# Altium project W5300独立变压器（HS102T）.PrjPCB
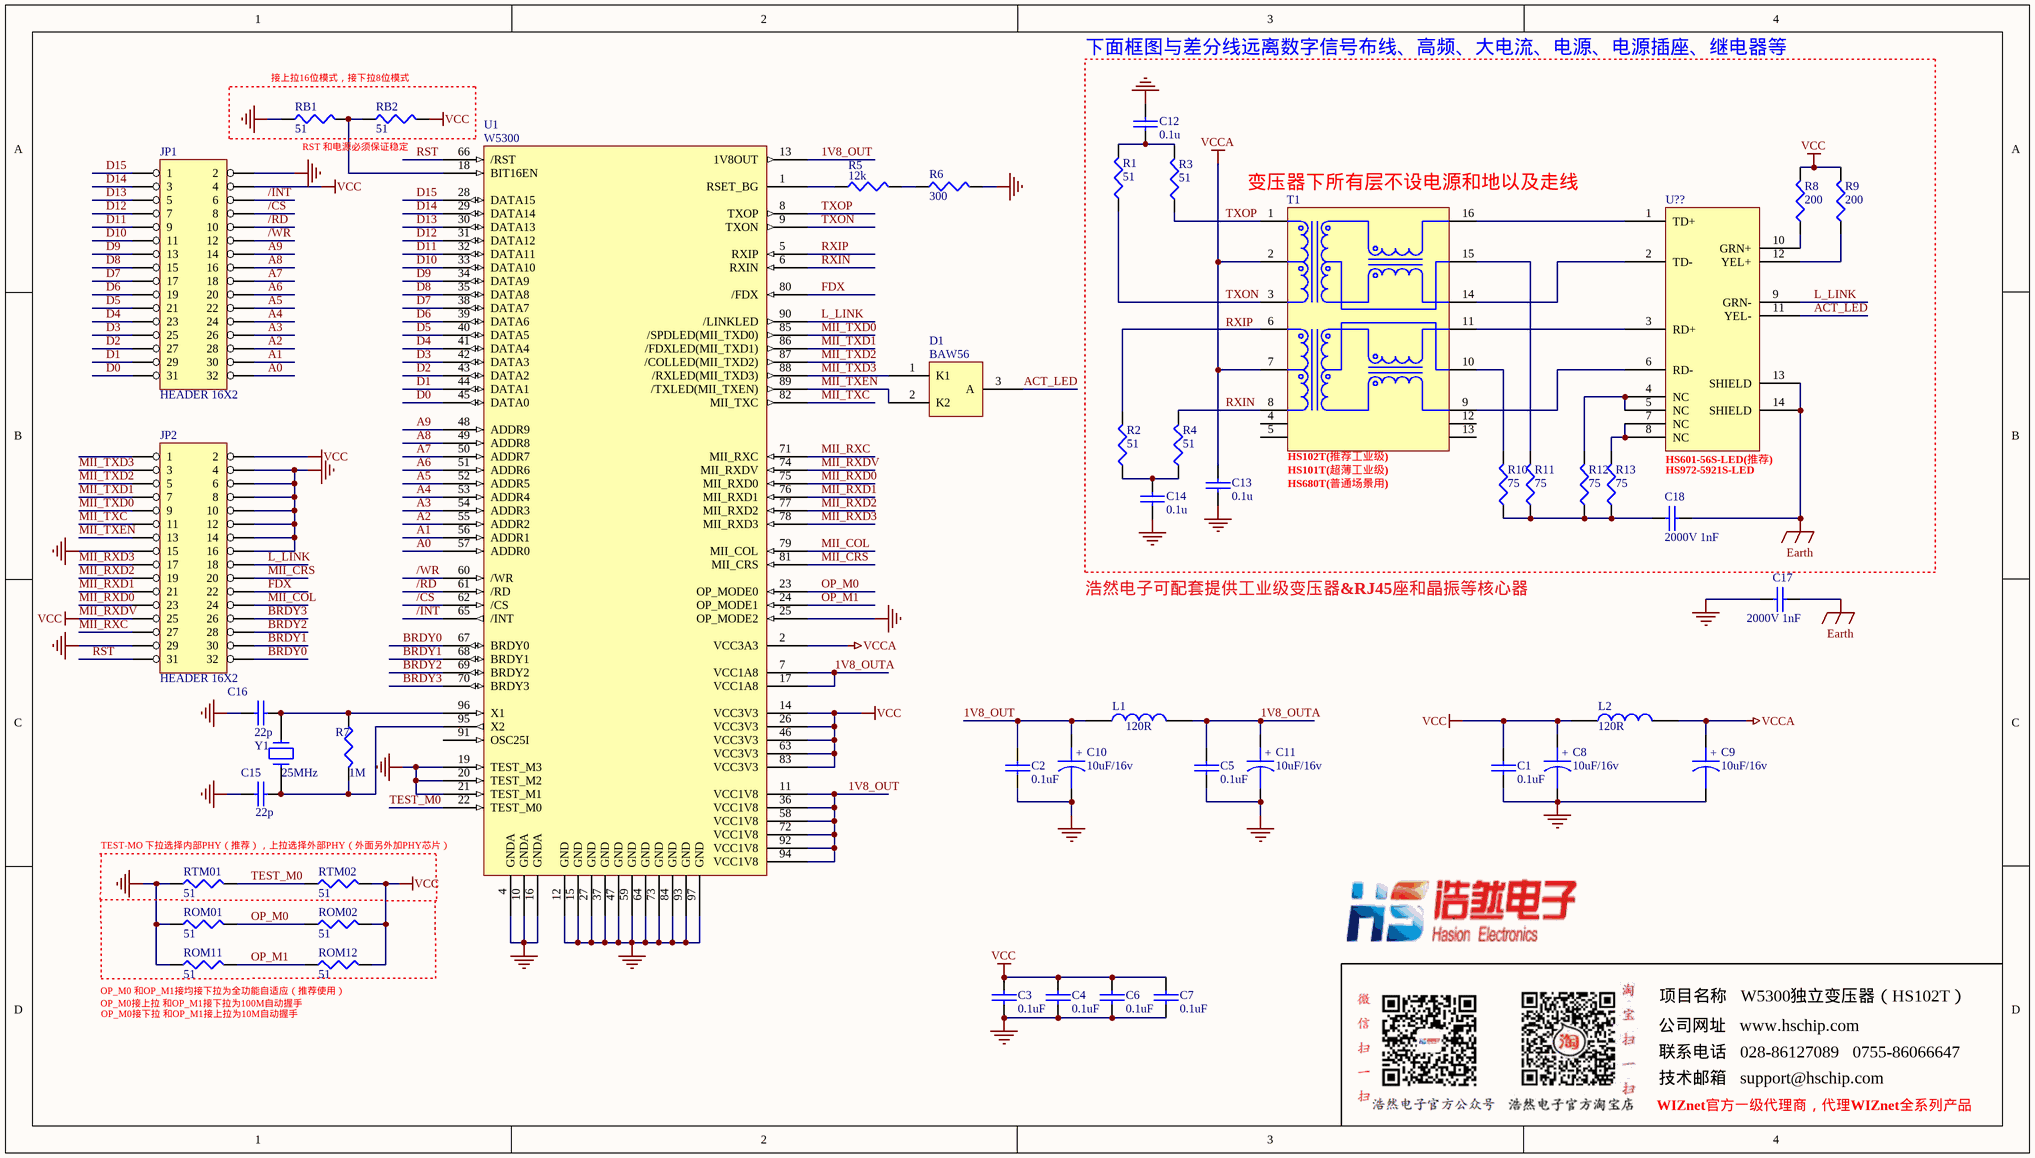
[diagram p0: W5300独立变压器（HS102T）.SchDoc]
1 sheet, 48 parts. Net scope: global (net labels, ports and power ports of the same name join across sheets).
Board file: PCB1.PcbDoc

## Sheet W5300独立变压器（HS102T）.SchDoc
size 381 x 215 mm; SheetNumber: 0; SheetTotal: 0; PageSetup: Record=PageOptions?CenterHorizontal=True?CenterVertical=True?PrintScale=0.77?XCorrection=1.00?YCorrection=1.00?PrintKind=0?BorderSize=5000000?LeftOffset=0?BottomOffset=0?Orientation=2?PaperLength=1000?PaperWidth=1000?Scale=100?PaperSource=7?PrintQuality=-4?MediaType=1?DitherType=10?PaperKind=A4?PrintScaleMode=1

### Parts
C1  0.1uF  [0603]
C2  0.1uF  [0603]
C3  0.1uF  [0603]
C4  0.1uF  [0603]
C5  0.1uF  [0603]
C6  0.1uF  [0603]
C7  0.1uF  [0603]
C8  10uF/16v  [3216]
C9  10uF/16v  [3216]
C10  10uF/16v  [3216]
C11  10uF/16v  [3216]
C12  0.1u  [0603]
C13  0.1u  [0603]
C14  0.1u  [0603]
C15  22p  [0603]
C16  22p  [0603]
C17  2000V 1nF  [3216]
C18  2000V 1nF  [3216]
D1  BAW56  [SOT-23]
JP1  HEADER 16X2  [IDC32-2]
JP2  HEADER 16X2  [IDC32-2]
L1  120R  [0603]
L2  120R  [0603]
R1  51  [0603]
R2  51  [0603]
R3  51  [0603]
R4  51  [0603]
R5  12k  [0603]
R6  300  [0603]
R7  1M  [0603]
R8  200  [0603]
R9  200  [0603]
R10  75  [0603]
R11  75  [0603]
R12  75  [0603]
R13  75  [0603]
RB1  51  [0603]
RB2  51  [0603]
ROM01  51  [0603]
ROM02  51  [0603]
ROM11  51  [0603]
ROM12  51  [0603]
RTM01  51  [0603]
RTM02  51  [0603]
T1  HS102T(推荐工业级)  [TR-HS101T/HS102T/HS680T]
U1  W5300  [LQFP100-W5300/VCT6]
U??  HS601-56S-LED(推荐)  [RJ45-HS601-56S-LED]
Y1  25MHz  [XTAL-49S]

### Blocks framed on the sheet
接上拉16位模式，接下拉8位模式: RB1 RB2
TEST-MO 下拉选择内部PHY（推荐），上拉选择外部PHY（外面另外加PHY芯片）: RTM01 RTM02

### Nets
Earth: C17.1 C18.1 U??.13(SHIELD) U??.14(SHIELD)
GND: C1.2 C2.2 C3.2 C4.2 C5.2 C6.2 C7.2 C8.2 C9.2 C10.2 C11.2 C12.1 C13.1 C14.2 C15.1 C16.1 C17.2 JP1.2 JP2.4 JP2.6 JP2.8 JP2.10 JP2.12 JP2.14 JP2.15 JP2.16 JP2.29 R6.2 RB1.1 ROM01.1 ROM11.1 RTM01.1 U1.4(GNDA) U1.10(GNDA) U1.12(GND) U1.15(GND) U1.16(GNDA) U1.19(TEST_M3) U1.20(TEST_M2) U1.21(TEST_M1) U1.25(OP_MODE2) U1.27(GND) U1.37(GND) U1.47(GND) U1.59(GND) U1.64(GND) U1.73(GND) U1.84(GND) U1.93(GND) U1.97(GND)
MII_RXDV: C1.1 C3.1 C4.1 C6.1 C7.1 C8.1 JP1.4 JP2.2 JP2.25 L2.1 R8.2 R9.2 RB2.2 ROM02.2 ROM12.2 RTM02.2 U1.14(VCC3V3) U1.26(VCC3V3) U1.46(VCC3V3) U1.63(VCC3V3) U1.74(MII_RXDV) U1.83(VCC3V3)  [also labelled VCC]
VCCA: C9.1 C13.2 L2.2 T1.2(CT) T1.7(CT) U1.2(VCC3A3)
1V8_OUT: C2.1 C10.1 L1.1 U1.11(VCC1V8) U1.13(1V8OUT) U1.36(VCC1V8) U1.58(VCC1V8) U1.72(VCC1V8) U1.92(VCC1V8) U1.94(VCC1V8)
1V8_OUTA: C5.1 C11.1 L1.2 U1.7(VCC1A8) U1.17(VCC1A8)
/CS: JP1.8 U1.62(/CS)
/INT: JP1.6 U1.65(/INT)
/RD: JP1.10 U1.61(/RD)
/WR: JP1.12 U1.60(/WR)
A0: JP1.32 U1.57(ADDR0)
A1: JP1.30 U1.56(ADDR1)
A2: JP1.28 U1.55(ADDR2)
A3: JP1.26 U1.54(ADDR3)
A4: JP1.24 U1.53(ADDR4)
A5: JP1.22 U1.52(ADDR5)
A6: JP1.20 U1.51(ADDR6)
A7: JP1.18 U1.50(ADDR7)
A8: JP1.16 U1.49(ADDR8)
A9: JP1.14 U1.48(ADDR9)
ACT_LED: D1.3(A) U??.11(YEL-)
BRDY0: JP2.32 U1.67(BRDY0)
BRDY1: JP2.30 U1.68(BRDY1)
BRDY2: JP2.28 U1.69(BRDY2)
BRDY3: JP2.26 U1.70(BRDY3)
D0: JP1.31 U1.45(DATA0)
D1: JP1.29 U1.44(DATA1)
D2: JP1.27 U1.43(DATA2)
D3: JP1.25 U1.42(DATA3)
D4: JP1.23 U1.41(DATA4)
D5: JP1.21 U1.40(DATA5)
D6: JP1.19 U1.39(DATA6)
D7: JP1.17 U1.38(DATA7)
D8: JP1.15 U1.35(DATA8)
D9: JP1.13 U1.34(DATA9)
D10: JP1.11 U1.33(DATA10)
D11: JP1.9 U1.32(DATA11)
D12: JP1.7 U1.31(DATA12)
D13: JP1.5 U1.30(DATA13)
D14: JP1.3 U1.29(DATA14)
D15: JP1.1 U1.28(DATA15)
FDX: JP2.22 U1.80(/FDX)
L_LINK: JP2.18 U1.90(/LINKLED) U??.9(GRN-)
MII_COL: JP2.24 U1.79(MII_COL)
MII_CRS: JP2.20 U1.81(MII_CRS)
MII_RXC: JP2.27 U1.71(MII_RXC)
MII_RXD0: JP2.23 U1.75(MII_RXD0)
MII_RXD1: JP2.21 U1.76(MII_RXD1)
MII_RXD2: JP2.19 U1.77(MII_RXD2)
MII_RXD3: JP2.17 U1.78(MII_RXD3)
MII_TXC: JP2.11 U1.82(MII_TXC)
MII_TXD0: JP2.9 U1.85(/SPDLED(MII_TXD0))
MII_TXD1: JP2.7 U1.86(/FDXLED(MII_TXD1))
MII_TXD2: JP2.5 U1.87(/COLLED(MII_TXD2))
MII_TXD3: D1.1(K1) JP2.3 U1.88(/RXLED(MII_TXD3))
MII_TXEN: D1.2(K2) JP2.13 U1.89(/TXLED(MII_TXEN))
OP_M0: ROM01.2 ROM02.1 U1.23(OP_MODE0)
OP_M1: ROM11.2 ROM12.1 U1.24(OP_MODE1)
RST: JP2.31 U1.66(/RST)
RXIN: R4.2 T1.8(RD-) U1.6(RXIN)
RXIP: U1.5(RXIP)
TEST_M0: RTM01.2 RTM02.1 U1.22(TEST_M0)
TXON: R1.1 T1.3(TD-) U1.9(TXON)
TXOP: R3.1 T1.1(TD+) U1.8(TXOP)
NetC12_2: C12.2 R1.2 R3.2
NetC14_1: C14.1 R2.1 R4.1
NetC15_2: C15.2 R7.1 U1.95(X2) Y1.1
NetC16_2: C16.2 R7.2 U1.96(X1) Y1.2
NetC18_2: C18.2 R10.1 R11.1 R12.1 R13.1
NetR2_2: R2.2 T1.6(RD+)
NetR5_1: R5.1 U1.1(RSET_BG)
NetR5_2: R5.2 R6.1
NetR8_1: R8.1 U??.10(GRN+)
NetR9_1: R9.1 U??.12(YEL+)
NetR10_2: R10.2 T1.10(CT)
NetR11_2: R11.2 T1.15(CT)
NetR12_2: R12.2 U??.4(NC) U??.5(NC)
NetR13_2: R13.2 U??.7(NC) U??.8(NC)
NetRB1_2: RB1.2 RB2.1 U1.18(BIT16EN)
NetT1_9: T1.9(RX-) U??.6(RD-)
NetT1_11: T1.11(RX+) U??.3(RD+)
NetT1_14: T1.14(TX-) U??.2(TD-)
NetT1_16: T1.16(TX+) U??.1(TD+)

Not connected (* = marked no-connect by the designer): JP2 1; T1 4 5 12 13; U1 91(OSC25I)

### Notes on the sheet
- 下面框图与差分线远离数字信号布线、高频、大电流、电源、电源插座、继电器等
- RST 和电源必须保证稳定
- (near T1) 变压器下所有层不设电源和地以及走线
- (near T1) HS101T(超薄工业级)
- (near T1) HS680T(普通场景用)
- HS972-5921S-LED
- (near ROM11) OP_M0 和OP_M1接均接下拉为全功能自适应（推荐使用）
- (near ROM11) OP_M0接上拉 和OP_M1接下拉为100M自动握手
- (near ROM11) OP_M0接下拉 和OP_M1接上拉为10M自动握手
- 公司网址   www.hschip.com
- 项目名称   W5300独立变压器（HS102T）
- WIZnet官方一级代理商，代理WIZnet全系列产品
- 联系电话   028-86127089   0755-86066647
- 技术邮箱   support@hschip.com
- Labels drawn without touching a wire or pin: RXIP, 浩然电子可配套提供工业级变压器&RJ45座和晶振等核心器

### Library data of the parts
C1-C7 C12-C18 = CAP: Capacitor
C8-C11 = CAPACITOR POL: Capacitor
L1 L2 = INDUCTOR
R1-R13 RB1 RB2 ROM01 ROM02 ROM11 ROM12 RTM01 RTM02 = RES1
T1 = HS102T: 版本号: R1.00; 日期: 2008年10月25日; 发行商: VRong LTD.; 赋值: USB
U1 = W5300: W5100
U?? = HS601 /HS972
Y1 = CRYSTAL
